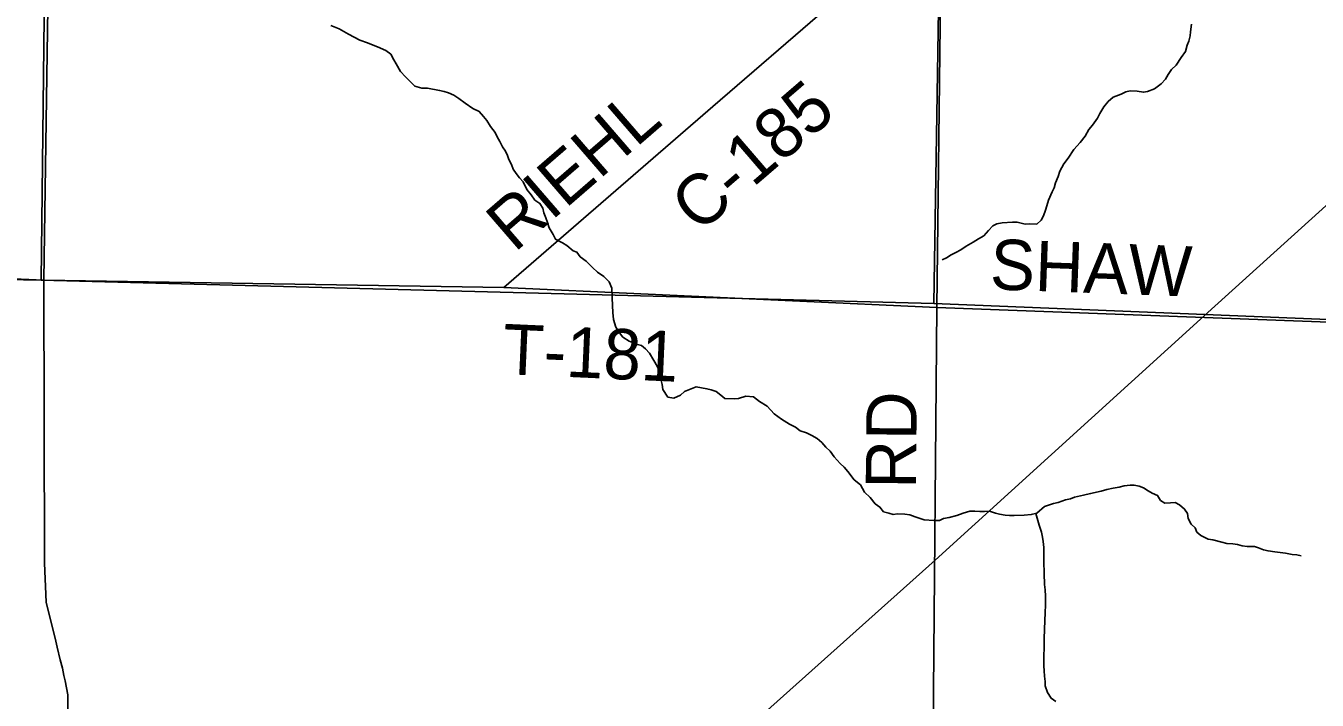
# Model space of a CAD drawing. Extents: x 0 to 34, y 0 to 22.
# Drawn here: x 3.441 to 4.9, y 15.033 to 15.795 of the extents above; entities that cross this region are included whole.
import ezdxf

# ---------------------------------------------------------------- set-up
doc = ezdxf.new("R2010")
doc.units = 0
for name, color, linetype in [('GM_X_County_Road', 7, 'Continuous'), ('GM_X_County_Road_Text', 7, 'Continuous'), ('GM_X_Minor_River', 7, 'Continuous'), ('GM_X_Rail_Line', 7, 'Continuous'), ('GM_X_Section', 7, 'Continuous'), ('GM_X_State_Route', 7, 'Continuous'), ('GM_X_Township_Road', 7, 'Continuous'), ('GM_X_Township_Road_Text', 7, 'Continuous')]:
    doc.layers.add(name, color=color, linetype=linetype)

msp = doc.modelspace()

# ---------------------------------------------------------------- linework, layer by layer
at = {"layer": 'GM_X_County_Road'}
msp.add_line((3.4615, 15.5078), (3.9812, 15.4992), dxfattribs=at)
for points in [[(3.9812, 15.4992), (4.2172, 15.704), (4.4759, 15.927), (4.8499, 16.2614), (4.9696, 16.3635), (5.1729, 16.5392), (5.2364, 16.5952)], [(2.4438, 15.5292), (2.4519, 15.5304), (2.4695, 15.5303), (2.6138, 15.5274), (3.0538, 15.5169), (3.3677, 15.5116), (3.4615, 15.5078)]]:
    msp.add_lwpolyline(points, dxfattribs=at)
at = {"layer": 'GM_X_Minor_River'}
for points in [[(3.7856, 15.7954), (3.7951, 15.7915), (3.8056, 15.7857), (3.8184, 15.7787), (3.8271, 15.7756), (3.8317, 15.774), (3.8385, 15.7713), (3.8479, 15.767), (3.8535, 15.7628), (3.8569, 15.7567), (3.8595, 15.7521), (3.8643, 15.7433), (3.8699, 15.7372), (3.8759, 15.7314), (3.8804, 15.7268), (3.8884, 15.7245), (3.8948, 15.7244), (3.9085, 15.722), (3.9138, 15.7208), (3.9187, 15.7192), (3.9247, 15.7165), (3.9304, 15.713), (3.9375, 15.7076), (3.9462, 15.7014), (3.9533, 15.698), (3.9582, 15.6926), (3.9619, 15.688), (3.966, 15.6811), (3.9713, 15.6746), (3.9735, 15.6696), (3.9765, 15.6643), (3.9798, 15.6582), (3.9832, 15.6532), (3.9854, 15.6486)], [(4.7582, 15.7968), (4.757, 15.788), (4.7566, 15.7835), (4.7553, 15.7778), (4.7534, 15.7733), (4.7514, 15.7661), (4.7464, 15.7593), (4.741, 15.7506), (4.7356, 15.7457), (4.7318, 15.7401), (4.7287, 15.7348), (4.7241, 15.7295), (4.7164, 15.7239), (4.7084, 15.7206), (4.7039, 15.7199), (4.6967, 15.7211), (4.6891, 15.7216), (4.6841, 15.7205), (4.6788, 15.7179), (4.6697, 15.7142), (4.6639, 15.7093), (4.6593, 15.7033), (4.6547, 15.6961), (4.6519, 15.6908), (4.6465, 15.6829), (4.6423, 15.678), (4.6381, 15.6705), (4.6323, 15.663), (4.6254, 15.6551), (4.6188, 15.6453), (4.6138, 15.6392), (4.6095, 15.6306), (4.6076, 15.6249), (4.6045, 15.6177), (4.6029, 15.612), (4.6009, 15.6075), (4.5966, 15.598), (4.5947, 15.5916), (4.5931, 15.5867), (4.5908, 15.5803), (4.5884, 15.5754), (4.5834, 15.5709), (4.5747, 15.5713), (4.5702, 15.571), (4.5611, 15.573), (4.5558, 15.573), (4.5444, 15.5724), (4.5383, 15.5713), (4.5337, 15.5691), (4.5287, 15.5638), (4.5234, 15.5578), (4.5176, 15.5545), (4.5115, 15.5504), (4.5035, 15.5459), (4.4974, 15.5418), (4.492, 15.5388), (4.4867, 15.5362), (4.4813, 15.5328), (4.4764, 15.5306)], [(3.9854, 15.6486), (3.9868, 15.6441), (3.9898, 15.6383), (3.9917, 15.633), (3.995, 15.628), (3.9987, 15.6234), (4.0029, 15.6188), (4.0073, 15.6101), (4.0122, 15.6039), (4.0163, 15.5982), (4.0219, 15.5943), (4.0253, 15.589), (4.0264, 15.5837), (4.0286, 15.5779), (4.0304, 15.5726), (4.0322, 15.5669), (4.0367, 15.5593), (4.0397, 15.5539), (4.0476, 15.55), (4.0525, 15.5469), (4.0593, 15.5408), (4.0638, 15.5392), (4.0675, 15.5339), (4.0743, 15.5292), (4.0814, 15.522), (4.0871, 15.5166), (4.0942, 15.5119), (4.1002, 15.5058), (4.1032, 15.4986), (4.1034, 15.4876), (4.1041, 15.4792), (4.1044, 15.4712), (4.105, 15.4632), (4.1076, 15.4545), (4.1117, 15.448), (4.1158, 15.4434), (4.1226, 15.4388), (4.132, 15.4349), (4.1366, 15.4337), (4.1414, 15.4302), (4.1456, 15.4252), (4.1508, 15.4168), (4.1545, 15.4103), (4.1571, 15.405), (4.1582, 15.4004), (4.1589, 15.3943), (4.16, 15.3898), (4.161, 15.3841), (4.1666, 15.3756), (4.1731, 15.3744), (4.1807, 15.3778), (4.1853, 15.3819), (4.1986, 15.3871), (4.2107, 15.385), (4.2153, 15.3839), (4.2209, 15.3819), (4.2262, 15.3777), (4.2307, 15.3738), (4.2417, 15.3737), (4.2463, 15.374), (4.2546, 15.3766), (4.2634, 15.3757), (4.2701, 15.3704), (4.2788, 15.3653), (4.2866, 15.3565), (4.2949, 15.3507), (4.304, 15.3449), (4.3108, 15.3414), (4.316, 15.3376), (4.3232, 15.3352), (4.3292, 15.3321), (4.3353, 15.3287), (4.3405, 15.3241), (4.345, 15.3191), (4.3499, 15.3145), (4.3544, 15.308), (4.3611, 15.3007), (4.3656, 15.2964), (4.3697, 15.2915), (4.3772, 15.2819), (4.384, 15.2765), (4.3888, 15.2681), (4.3952, 15.2623), (4.4008, 15.2551), (4.4061, 15.2512), (4.4102, 15.2459), (4.4162, 15.2443), (4.4212, 15.2431), (4.4261, 15.2438), (4.4341, 15.2433), (4.4401, 15.2425), (4.4458, 15.2402), (4.4503, 15.2386), (4.456, 15.237), (4.467, 15.2361), (4.4734, 15.2361), (4.478, 15.2383), (4.4845, 15.2397), (4.4932, 15.2419), (4.5001, 15.2445), (4.5077, 15.2467)], [(4.5077, 15.2467), (4.5134, 15.2467), (4.5191, 15.2462), (4.5244, 15.2462), (4.5301, 15.2465), (4.5369, 15.2445), (4.5414, 15.2433), (4.5478, 15.2421), (4.5524, 15.2417), (4.5577, 15.2416), (4.5691, 15.2423), (4.5771, 15.2429), (4.5835, 15.2444), (4.5923, 15.2519), (4.6022, 15.2552), (4.6075, 15.2563), (4.6159, 15.2596), (4.6216, 15.2607), (4.6262, 15.2625), (4.6361, 15.2647), (4.6441, 15.2665), (4.6563, 15.2694), (4.6627, 15.2712), (4.6699, 15.2727), (4.6764, 15.2738), (4.6821, 15.2752), (4.6889, 15.2759), (4.6935, 15.2759), (4.6992, 15.275), (4.7041, 15.2731), (4.7094, 15.2696), (4.7139, 15.2669), (4.7199, 15.2642), (4.7233, 15.2588), (4.7282, 15.2557), (4.7346, 15.256), (4.7396, 15.2564), (4.7445, 15.254), (4.7505, 15.249), (4.7538, 15.2441), (4.7545, 15.2384), (4.7579, 15.2319), (4.7624, 15.228), (4.7642, 15.2231), (4.7687, 15.2192), (4.777, 15.215), (4.7823, 15.2142), (4.7925, 15.2118), (4.7982, 15.2102), (4.805, 15.2097), (4.8103, 15.2089), (4.8156, 15.2074), (4.8213, 15.2069), (4.8293, 15.2068), (4.8338, 15.2053), (4.8395, 15.2029), (4.8448, 15.2017), (4.8523, 15.2009), (4.8645, 15.1992), (4.872, 15.1976), (4.8773, 15.1972), (4.8823, 15.1964)], [(4.5822, 15.2441), (4.586, 15.2307), (4.5886, 15.2231), (4.59, 15.2174), (4.5907, 15.2124), (4.5914, 15.2056), (4.5912, 15.19), (4.5918, 15.1763), (4.5921, 15.1638), (4.5928, 15.1577), (4.5931, 15.1505), (4.5933, 15.1418), (4.5928, 15.1312), (4.5924, 15.1239), (4.5923, 15.1122), (4.5918, 15.1035), (4.5914, 15.0719), (4.5917, 15.0663), (4.592, 15.0602), (4.5927, 15.0541), (4.5927, 15.0495), (4.5956, 15.0419), (4.5997, 15.0354), (4.605, 15.0316)]]:
    msp.add_lwpolyline(points, dxfattribs=at)
at = {"layer": 'GM_X_Rail_Line'}
msp.add_lwpolyline([(3.6815, 14.4919), (3.8612, 14.6519), (4.1651, 14.9197), (4.4686, 15.1913), (4.7768, 15.471), (5.1412, 15.8006), (5.4601, 16.0872), (6.2018, 16.7592), (6.7493, 17.2493), (7.0065, 17.4955), (7.1712, 17.6375), (7.3789, 17.8309), (7.4524, 17.8921)], dxfattribs=at)
at = {"layer": 'GM_X_Section'}
for points in [[(3.4692, 16.4646), (3.4584, 15.5077), (2.4379, 15.527), (2.4859, 16.423), (2.4877, 16.4726)], [(4.4826, 16.453), (4.4671, 15.4814), (3.4584, 15.5077), (3.4692, 16.4646)], [(5.4956, 16.4418), (5.4878, 15.4398), (4.4671, 15.4814), (4.4826, 16.453)]]:
    msp.add_lwpolyline(points, close=True, dxfattribs=at)
at = {"layer": 'GM_X_State_Route'}
for points in [[(3.462, 15.1881), (3.4615, 15.5078), (3.4661, 15.8411), (3.4739, 16.2421), (3.4802, 16.6496)], [(3.4747, 15.0999), (3.464, 15.1439), (3.462, 15.1881)], [(3.4841, 15.061), (3.4823, 15.0692), (3.4798, 15.0787), (3.4763, 15.0932), (3.4747, 15.0999)], [(3.4883, 15.0212), (3.4886, 15.0393), (3.4855, 15.0549), (3.4841, 15.061)]]:
    msp.add_lwpolyline(points, dxfattribs=at)
at = {"layer": 'GM_X_Township_Road'}
for p, q in [((4.4706, 15.4769), (4.4759, 15.927)), ((4.4614, 14.477), (4.4706, 15.4769))]:
    msp.add_line(p, q, dxfattribs=at)
msp.add_lwpolyline([(3.9812, 15.4992), (4.4706, 15.4769), (5.9317, 15.422)], dxfattribs=at)

# ---------------------------------------------------------------- texts
at = {"layer": 'GM_X_County_Road_Text'}
for s, rotation, p in [('C-185', 40.7203, (4.2018, 15.5594)), ('RIEHL', 40.8551, (3.9932, 15.5381))]:
    msp.add_text(s, height=0.05682, rotation=rotation, dxfattribs=at).set_placement(p)
at = {"layer": 'GM_X_Township_Road_Text'}
for s, rotation, p in [('SHAW', 357.8965, (4.5299, 15.4974)), ('T-181', 357.4736, (3.9789, 15.4016)), ('RD', 89.5063, (4.4469, 15.2719))]:
    msp.add_text(s, height=0.05682, rotation=rotation, dxfattribs=at).set_placement(p)

doc.saveas('drawing.dxf')
